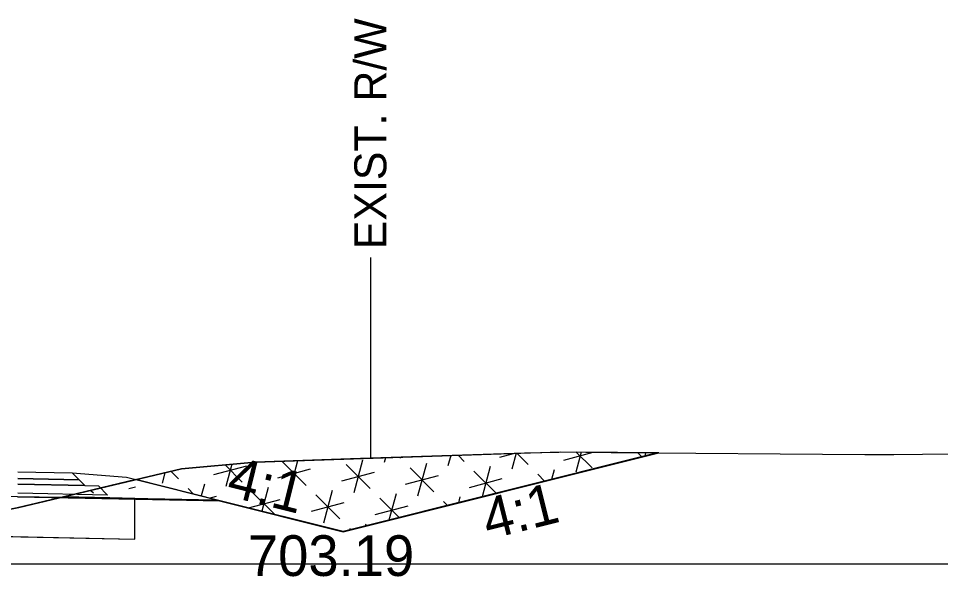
# Model space of a CAD drawing. Extents: x -26 to 4303, y -10 to 9577.
# Drawn here: x 2167.02 to 2201.04, y 7499.53 to 7520.1 of the extents above; entities that cross this region are included whole.
import ezdxf

# ---------------------------------------------------------------- set-up
doc = ezdxf.new("R2010")
doc.units = 0
for name, color, linetype in [('Old_Level_2', 7, 'Continuous'), ('Pattern 3', 7, 'Continuous'), ('Prop CMT Pvmt Course 2', 7, 'Continuous'), ('Prop CMT Pvmt Course 2 Wedge', 7, 'Continuous'), ('Prop CMT Pvmt Course 3', 7, 'Continuous'), ('Prop CMT Pvmt Wedge Surface 1', 7, 'Continuous'), ('Prop CMT Shld Paved Course 2', 7, 'Continuous'), ('Prop CMT Slope Grass', 7, 'Continuous'), ('Prop CMT Subgrade Earthwork', 7, 'Continuous'), ('Prop Road Sect_ Recs - UC Shallow (Outline)', 7, 'Continuous'), ('Prop Shade Light', 7, 'Continuous'), ('Prop XS DDE Elevations', 7, 'Continuous'), ('Prop XS Ditch Standard Text', 7, 'Continuous'), ('Prop XS Hydro Elevations', 7, 'Continuous'), ('Prop XS Side Slope Text', 7, 'Continuous'), ('Scratch_Level_2', 7, 'Continuous')]:
    doc.layers.add(name, color=color, linetype=linetype)

msp = doc.modelspace()

# ---------------------------------------------------------------- linework, layer by layer
at = {"layer": 'Old_Level_2'}
msp.add_line((2150, 7500), (2300, 7500), dxfattribs=at)
msp.add_line((2150, 7500), (2300, 7500), dxfattribs=at)
at = {"layer": 'Pattern 3'}
for p, q in [((2179.71, 7503.818), (2179.387, 7502.611)), ((2180.553, 7503.908), (2180.506, 7503.73)), ((2181.075, 7503.926), (2181.109, 7503.891)), ((2182.964, 7503.99), (2182.862, 7503.611)), ((2183.239, 7504), (2183.466, 7503.773)), ((2184.777, 7503.935), (2185.278, 7504.069)), ((2185.374, 7504.072), (2185.219, 7503.493)), ((2185.404, 7504.073), (2185.822, 7503.655)), ((2187.133, 7503.816), (2188.222, 7504.108)), ((2187.774, 7504.115), (2187.575, 7503.374)), ((2187.597, 7504.118), (2188.179, 7503.536)), ((2189.862, 7504.091), (2190.011, 7503.942)), ((2190.155, 7504.089), (2190.123, 7503.969)), ((2174.232, 7503.289), (2175.439, 7503.613)), ((2174.64, 7503.646), (2175.277, 7503.009)), ((2174.894, 7503.669), (2174.674, 7502.847)), ((2176.588, 7503.171), (2177.796, 7503.495)), ((2176.75, 7503.775), (2177.634, 7502.891)), ((2177.317, 7503.798), (2177.03, 7502.729)), ((2179.106, 7503.656), (2179.99, 7502.772)), ((2181.463, 7503.538), (2182.347, 7502.654)), ((2182.067, 7503.7), (2181.743, 7502.492)), ((2184.423, 7503.581), (2184.125, 7502.47)), ((2186.78, 7503.463), (2186.685, 7503.11)), ((2172.422, 7503.358), (2172.317, 7502.966)), ((2172.639, 7503.41), (2172.921, 7503.128)), ((2178.945, 7503.053), (2180.152, 7503.376)), ((2181.301, 7502.934), (2182.509, 7503.258)), ((2183.658, 7502.816), (2184.865, 7503.139)), ((2183.819, 7503.419), (2184.64, 7502.599)), ((2186.176, 7503.301), (2186.43, 7503.046)), ((2173.878, 7502.936), (2173.761, 7502.499)), ((2176.235, 7502.817), (2175.999, 7501.939)), ((2173.275, 7502.774), (2173.48, 7502.569)), ((2174.059, 7502.424), (2174.32, 7502.494)), ((2175.631, 7502.656), (2176.464, 7501.823)), ((2177.987, 7502.537), (2178.871, 7501.653)), ((2178.591, 7502.699), (2178.268, 7501.492)), ((2180.948, 7502.581), (2180.688, 7501.611)), ((2183.304, 7502.462), (2183.247, 7502.251)), ((2175.507, 7502.062), (2176.677, 7502.375)), ((2177.826, 7501.934), (2179.033, 7502.257)), ((2180.182, 7501.815), (2181.39, 7502.139)), ((2180.344, 7502.419), (2181.059, 7501.704)), ((2182.7, 7502.3), (2182.85, 7502.151)), ((2177.472, 7501.58), (2177.47, 7501.571)), ((2179.829, 7501.462), (2179.81, 7501.391)), ((2179.225, 7501.3), (2179.269, 7501.256))]:
    msp.add_line(p, q, dxfattribs=at)
msp.add_lwpolyline([(2168.682, 7502.464), (2174.283, 7502.352), (2179, 7501.173), (2190.647, 7504.085), (2187.597, 7504.118), (2185.686, 7504.083), (2182.64, 7503.979), (2179.265, 7503.864), (2175.746, 7503.744), (2173.032, 7503.503)], close=True, dxfattribs=at)
at = {"layer": 'Prop CMT Pvmt Course 2'}
for points in [[(2167, 7503.389), (2169, 7503.349), (2169.255, 7503.094)], [(2169.255, 7503.094), (2167, 7503.139)]]:
    msp.add_lwpolyline(points, dxfattribs=at)
at = {"layer": 'Prop CMT Pvmt Course 2 Wedge'}
msp.add_lwpolyline([(2169, 7503.349), (2171, 7503.189), (2179, 7501.189), (2190.587, 7504.086)], dxfattribs=at)
at = {"layer": 'Prop CMT Pvmt Course 3'}
for points in [[(2167, 7503.139), (2169.255, 7503.094), (2169.468, 7502.881)], [(2169.468, 7502.881), (2167, 7502.931)]]:
    msp.add_lwpolyline(points, dxfattribs=at)
at = {"layer": 'Prop CMT Pvmt Wedge Surface 1'}
msp.add_line((2166.982, 7502.472), (2174.465, 7502.323), dxfattribs=at)
at = {"layer": 'Prop CMT Shld Paved Course 2'}
msp.add_lwpolyline([(2167, 7503.389), (2169, 7503.349)], dxfattribs=at)
at = {"layer": 'Prop CMT Slope Grass'}
msp.add_lwpolyline([(2165.593, 7501.789), (2167.035, 7502.071), (2173.032, 7503.504), (2175.746, 7503.744), (2186.999, 7504.128), (2188.879, 7504.098), (2198.245, 7504.032), (2199.314, 7504.025), (2208.803, 7504.133)], dxfattribs=at)
at = {"layer": 'Prop CMT Subgrade Earthwork'}
for points in [[(2167, 7502.931), (2169.468, 7502.881), (2169.968, 7502.871), (2170.308, 7502.531)], [(2170.308, 7502.531), (2167, 7502.597)]]:
    msp.add_lwpolyline(points, dxfattribs=at)
at = {"layer": 'Prop Road Sect_ Recs - UC Shallow (Outline)'}
msp.add_lwpolyline([(2162.283, 7502.592), (2162.281, 7501.092), (2171.306, 7500.912), (2171.306, 7502.412), (2168.682, 7502.464), (2166.974, 7502.059), (2166.182, 7501.904), (2165.593, 7501.789), (2164.339, 7502.198), (2163.185, 7502.574), (2162.285, 7502.592)], close=True, dxfattribs=at)
at = {"layer": 'Prop Shade Light'}
for p, q in [((2168.682, 7502.464), (2167.035, 7502.071)), ((2170.393, 7502.43), (2168.682, 7502.464)), ((2171.306, 7502.412), (2170.393, 7502.43)), ((2171.306, 7500.912), (2171.306, 7502.412)), ((2167.035, 7502.071), (2165.593, 7501.789)), ((2162.281, 7501.092), (2171.306, 7500.912))]:
    msp.add_line(p, q, dxfattribs=at)
at = {"layer": 'Prop XS DDE Elevations'}
for points in [[(2175.746, 7503.744), (2186.999, 7504.128), (2188.879, 7504.098), (2190.587, 7504.086), (2179, 7501.189), (2174.465, 7502.323), (2171.349, 7503.102), (2173.032, 7503.504)], [(2168.58, 7502.44), (2174.465, 7502.323), (2171.349, 7503.102)], [(2167.035, 7502.071), (2168.58, 7502.44), (2166.982, 7502.472), (2163.27, 7502.546), (2165.593, 7501.789)]]:
    msp.add_lwpolyline(points, close=True, dxfattribs=at)
at = {"layer": 'Prop XS Ditch Standard Text'}
msp.add_line((2180, 7511.291), (2180, 7503.889), dxfattribs=at)
at = {"layer": 'Scratch_Level_2'}
for p, q in [((2171.096, 7502.776), (2171.33, 7502.839)), ((2169.219, 7502.593), (2169.209, 7502.553)), ((2169.694, 7502.706), (2169.786, 7502.614))]:
    msp.add_line(p, q, dxfattribs=at)

# ---------------------------------------------------------------- texts
at = {"layer": 'Prop XS Ditch Standard Text'}
msp.add_text('EXIST. R/W', height=1.1811, rotation=90, dxfattribs=at).set_placement((2180.591, 7511.593))
at = {"layer": 'Prop XS Hydro Elevations'}
msp.add_text('703.19', height=1.5, dxfattribs=at).set_placement((2175.483, 7499.551))
at = {"layer": 'Prop XS Side Slope Text'}
for rotation, p in [(345.9638, (2174.64, 7502.516)), (14.0362, (2184.349, 7500.885))]:
    msp.add_text('4:1', height=1.5, rotation=rotation, dxfattribs=at).set_placement(p)

doc.saveas('drawing.dxf')
